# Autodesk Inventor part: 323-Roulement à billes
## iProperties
Author: Philippe
Shininess: 60.0
Angle Display Precision: 2
Document Length Units: 11269
Document Angle Units: 11283
Document Time Units: 11279
Document Mass Units: 11290
Document Length Units Precision: 3
Document Angle Units Precision: 2
Compacted: False
PropertySet Name: _Private Model Information
Created: 2001-12
Part Number: 323-Roulement à billes
Material: Par défaut
Document SubType Name: Modélisation
Designer: Philippe
Control State: 0
Master: False
Checked Out: False
PropertySet Name: Design Tracking Control
Density: 0.0
Volumn: 0.0
Area: 0.0
PropertySet Name: Model Information
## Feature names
1. Révolution1 [Revolution]
2. Révolution2 [Revolution]
3. Réseau circulaire1 [Circular Pattern]
